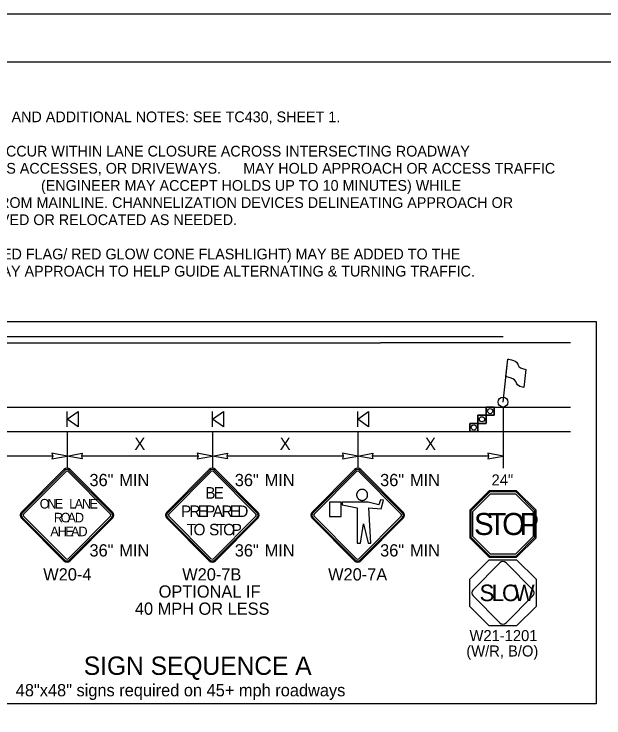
# Model space of a CAD drawing. Extents: x 99999.1 to 100095.7, y 99995 to 100010.7.
# Drawn here: x 100021.344 to 100025.2, y 100006.089 to 100010.687 of the extents above; entities that cross this region are included whole.
import ezdxf

# ---------------------------------------------------------------- set-up
doc = ezdxf.new("R2010")
doc.units = 0
for name, color, linetype in [('RD_ED_ShoulderPavedEdge', 7, 'Continuous'), ('RD_MK_LineDblYellowCenter', 7, 'Continuous'), ('RD_MK_LineEdgeWhite', 7, 'Continuous'), ('RD_MK_LineNoPass', 7, 'Continuous'), ('RD_MK_LineSkipCenter', 7, 'Continuous'), ('SH_DE_DetailHeading2Text', 7, 'Continuous'), ('SH_GI_GeneralNotesBodyText', 7, 'Continuous'), ('SH_GI_PlotLimits', 7, 'Continuous'), ('SH_GI_SheetBorder', 7, 'Continuous'), ('TR_SN_ConstructionSigns', 7, 'Continuous'), ('TR_WZ_FlaggingStation', 7, 'Continuous'), ('TR_WZ_PortableSignMountBlk-Org', 7, 'Continuous'), ('TR_WZ_TrafficCone', 7, 'Continuous'), ('TR_WZ_WorkZoneDetails', 7, 'Continuous'), ('TR_WZ_WorkZoneTextCurrent', 7, 'Continuous')]:
    doc.layers.add(name, color=color, linetype=linetype)

msp = doc.modelspace()

# ---------------------------------------------------------------- linework, layer by layer
at = {"layer": 'RD_ED_ShoulderPavedEdge'}
msp.add_line((100020.3, 100007.9602), (100024.9804, 100007.9602), dxfattribs=at)
at = {"layer": 'RD_MK_LineDblYellowCenter'}
for p, q in [((100020.3, 100008.5802), (100023.7402, 100008.5802)), ((100020.3, 100008.5402), (100023.7402, 100008.5402))]:
    msp.add_line(p, q, dxfattribs=at)
at = {"layer": 'RD_MK_LineEdgeWhite'}
msp.add_line((100020.3, 100008.1202), (100024.9804, 100008.1202), dxfattribs=at)
at = {"layer": 'RD_MK_LineNoPass'}
msp.add_line((100023.7402, 100008.5802), (100024.5402, 100008.5802), dxfattribs=at)
at = {"layer": 'RD_MK_LineSkipCenter'}
msp.add_lwpolyline([(100024.9804, 100008.5402), (100023.7402, 100008.5402)], dxfattribs=at)
at = {"layer": 'SH_GI_PlotLimits'}
msp.add_lwpolyline([(100019.0625, 99999.6875), (100036.0625, 99999.6875), (100036.0625, 100010.6875), (100019.0625, 100010.6875)], close=True, dxfattribs=at)
at = {"layer": 'SH_GI_SheetBorder'}
msp.add_line((100020, 100010.375), (100035.75, 100010.375), dxfattribs=at)
at = {"layer": 'TR_SN_ConstructionSigns'}
for p, q in [((100021.6703, 100007.712), (100021.3919, 100007.4336)), ((100021.6758, 100007.7065), (100021.3974, 100007.428)), ((100021.4051, 100007.4203), (100021.6835, 100007.6987)), ((100021.6968, 100007.6987), (100021.9752, 100007.4203)), ((100021.9829, 100007.428), (100021.7045, 100007.7065)), ((100021.9885, 100007.4336), (100021.71, 100007.712)), ((100022.6203, 100007.712), (100022.3419, 100007.4336)), ((100022.6258, 100007.7065), (100022.3474, 100007.428)), ((100022.3551, 100007.4203), (100022.6335, 100007.6987)), ((100022.6468, 100007.6987), (100022.9252, 100007.4203)), ((100022.9329, 100007.428), (100022.6545, 100007.7065)), ((100022.9385, 100007.4336), (100022.66, 100007.712)), ((100023.5703, 100007.712), (100023.2919, 100007.4336)), ((100023.5758, 100007.7065), (100023.2974, 100007.428)), ((100023.3051, 100007.4203), (100023.5835, 100007.6987)), ((100023.5968, 100007.6987), (100023.8752, 100007.4203)), ((100023.8829, 100007.428), (100023.6045, 100007.7065)), ((100023.8885, 100007.4336), (100023.61, 100007.712)), ((100023.6071, 100007.5803), (100023.6053, 100007.5796)), ((100023.6089, 100007.5809), (100023.6071, 100007.5803)), ((100023.6108, 100007.5814), (100023.6089, 100007.5809)), ((100023.6127, 100007.5818), (100023.6108, 100007.5814)), ((100023.6146, 100007.5821), (100023.6127, 100007.5818)), ((100023.6164, 100007.5823), (100023.6146, 100007.5821)), ((100023.6184, 100007.5824), (100023.6164, 100007.5823)), ((100023.6203, 100007.5824), (100023.6184, 100007.5824)), ((100023.6222, 100007.5823), (100023.6203, 100007.5824)), ((100023.6241, 100007.5821), (100023.6222, 100007.5823)), ((100023.626, 100007.5818), (100023.6241, 100007.5821)), ((100023.6279, 100007.5814), (100023.626, 100007.5818)), ((100023.6297, 100007.5809), (100023.6279, 100007.5814)), ((100023.6316, 100007.5803), (100023.6297, 100007.5809)), ((100023.6333, 100007.5796), (100023.6316, 100007.5803)), ((100023.5835, 100007.5502), (100023.5833, 100007.5483)), ((100023.5833, 100007.5483), (100023.5833, 100007.5464)), ((100023.5833, 100007.5464), (100023.5833, 100007.5445)), ((100023.5833, 100007.5445), (100023.5835, 100007.5426)), ((100023.5838, 100007.5522), (100023.5835, 100007.5502)), ((100023.5835, 100007.5426), (100023.5838, 100007.5407)), ((100023.5842, 100007.554), (100023.5838, 100007.5522)), ((100023.5838, 100007.5407), (100023.5842, 100007.5388)), ((100023.5846, 100007.5559), (100023.5842, 100007.554)), ((100023.5842, 100007.5388), (100023.5846, 100007.5369)), ((100023.5852, 100007.5577), (100023.5846, 100007.5559)), ((100023.5846, 100007.5369), (100023.5852, 100007.5351)), ((100023.5858, 100007.5595), (100023.5852, 100007.5577)), ((100023.5852, 100007.5351), (100023.5858, 100007.5333)), ((100023.5865, 100007.5613), (100023.5858, 100007.5595)), ((100023.5873, 100007.563), (100023.5865, 100007.5613)), ((100023.5883, 100007.5647), (100023.5873, 100007.563)), ((100023.5894, 100007.5664), (100023.5883, 100007.5647)), ((100023.5904, 100007.5679), (100023.5894, 100007.5664)), ((100023.5916, 100007.5694), (100023.5904, 100007.5679)), ((100023.5929, 100007.5709), (100023.5916, 100007.5694)), ((100023.5942, 100007.5722), (100023.5929, 100007.5709)), ((100023.5956, 100007.5735), (100023.5942, 100007.5722)), ((100023.5971, 100007.5747), (100023.5956, 100007.5735)), ((100023.5986, 100007.5759), (100023.5971, 100007.5747)), ((100023.6002, 100007.5769), (100023.5986, 100007.5759)), ((100023.6019, 100007.5779), (100023.6002, 100007.5769)), ((100023.6036, 100007.5788), (100023.6019, 100007.5779)), ((100023.6053, 100007.5796), (100023.6036, 100007.5788)), ((100023.6351, 100007.5788), (100023.6333, 100007.5796)), ((100023.6368, 100007.5779), (100023.6351, 100007.5788)), ((100023.6385, 100007.5769), (100023.6368, 100007.5779)), ((100023.64, 100007.5759), (100023.6385, 100007.5769)), ((100023.6416, 100007.5747), (100023.64, 100007.5759)), ((100023.643, 100007.5735), (100023.6416, 100007.5747)), ((100023.6445, 100007.5722), (100023.643, 100007.5735)), ((100023.6458, 100007.5709), (100023.6445, 100007.5722)), ((100023.647, 100007.5694), (100023.6458, 100007.5709)), ((100023.6482, 100007.5679), (100023.647, 100007.5694)), ((100023.6494, 100007.5664), (100023.6482, 100007.5679)), ((100023.6504, 100007.5647), (100023.6494, 100007.5664)), ((100023.6513, 100007.563), (100023.6504, 100007.5647)), ((100023.6521, 100007.5613), (100023.6513, 100007.563)), ((100023.6529, 100007.5595), (100023.6521, 100007.5613)), ((100023.6535, 100007.5577), (100023.6529, 100007.5595)), ((100023.6529, 100007.5333), (100023.6535, 100007.5351)), ((100023.6541, 100007.5559), (100023.6535, 100007.5577)), ((100023.6535, 100007.5351), (100023.6541, 100007.5369)), ((100023.6545, 100007.554), (100023.6541, 100007.5559)), ((100023.6541, 100007.5369), (100023.6545, 100007.5388)), ((100023.6549, 100007.5522), (100023.6545, 100007.554)), ((100023.6545, 100007.5388), (100023.6549, 100007.5407)), ((100023.6552, 100007.5502), (100023.6549, 100007.5522)), ((100023.6549, 100007.5407), (100023.6552, 100007.5426)), ((100023.6553, 100007.5483), (100023.6552, 100007.5502)), ((100023.6552, 100007.5426), (100023.6553, 100007.5445)), ((100023.6554, 100007.5464), (100023.6553, 100007.5483)), ((100023.6553, 100007.5445), (100023.6554, 100007.5464)), ((100024.4506, 100007.5722), (100024.3241, 100007.4457)), ((100024.4534, 100007.5655), (100024.3308, 100007.4429)), ((100024.3421, 100007.4383), (100024.4581, 100007.5542)), ((100024.6295, 100007.5722), (100024.4506, 100007.5722)), ((100024.6267, 100007.5655), (100024.4534, 100007.5655)), ((100024.4581, 100007.5542), (100024.6221, 100007.5542)), ((100024.6221, 100007.5542), (100024.7381, 100007.4383)), ((100024.7493, 100007.4429), (100024.6267, 100007.5655)), ((100024.7561, 100007.4457), (100024.6295, 100007.5722)), ((100023.4059, 100007.4991), (100023.4059, 100007.4044)), ((100023.4812, 100007.4991), (100023.4059, 100007.4991)), ((100023.4812, 100007.4044), (100023.4812, 100007.4991)), ((100023.6596, 100007.4991), (100023.4882, 100007.4991)), ((100023.4882, 100007.4991), (100023.4882, 100007.481)), ((100023.5858, 100007.5333), (100023.5865, 100007.5315)), ((100023.5865, 100007.5315), (100023.5873, 100007.5298)), ((100023.5873, 100007.5298), (100023.5883, 100007.5281)), ((100023.5883, 100007.5281), (100023.5894, 100007.5265)), ((100023.5894, 100007.5265), (100023.5904, 100007.5249)), ((100023.5904, 100007.5249), (100023.5916, 100007.5234)), ((100023.5916, 100007.5234), (100023.5929, 100007.522)), ((100023.5929, 100007.522), (100023.5942, 100007.5206)), ((100023.5942, 100007.5206), (100023.5956, 100007.5193)), ((100023.5956, 100007.5193), (100023.5971, 100007.5181)), ((100023.5971, 100007.5181), (100023.5986, 100007.5169)), ((100023.5986, 100007.5169), (100023.6002, 100007.5159)), ((100023.6002, 100007.5159), (100023.6019, 100007.5149)), ((100023.6019, 100007.5149), (100023.6036, 100007.514)), ((100023.6036, 100007.514), (100023.6053, 100007.5132)), ((100023.6053, 100007.5132), (100023.6071, 100007.5125)), ((100023.6071, 100007.5125), (100023.6089, 100007.5119)), ((100023.6089, 100007.5119), (100023.6108, 100007.5114)), ((100023.6108, 100007.5114), (100023.6127, 100007.511)), ((100023.6127, 100007.511), (100023.6146, 100007.5107)), ((100023.6146, 100007.5107), (100023.6164, 100007.5105)), ((100023.6164, 100007.5105), (100023.6184, 100007.5104)), ((100023.6184, 100007.5104), (100023.6203, 100007.5104)), ((100023.6203, 100007.5104), (100023.6222, 100007.5105)), ((100023.6222, 100007.5105), (100023.6241, 100007.5107)), ((100023.6241, 100007.5107), (100023.626, 100007.511)), ((100023.626, 100007.511), (100023.6279, 100007.5114)), ((100023.6279, 100007.5114), (100023.6297, 100007.5119)), ((100023.6297, 100007.5119), (100023.6316, 100007.5125)), ((100023.6316, 100007.5125), (100023.6333, 100007.5132)), ((100023.6333, 100007.5132), (100023.6351, 100007.514)), ((100023.6351, 100007.514), (100023.6368, 100007.5149)), ((100023.6368, 100007.5149), (100023.6385, 100007.5159)), ((100023.6385, 100007.5159), (100023.64, 100007.5169)), ((100023.64, 100007.5169), (100023.6416, 100007.5181)), ((100023.6416, 100007.5181), (100023.643, 100007.5193)), ((100023.643, 100007.5193), (100023.6445, 100007.5206)), ((100023.6445, 100007.5206), (100023.6458, 100007.522)), ((100023.6458, 100007.522), (100023.647, 100007.5234)), ((100023.647, 100007.5234), (100023.6482, 100007.5249)), ((100023.6482, 100007.5249), (100023.6494, 100007.5265)), ((100023.6494, 100007.5265), (100023.6504, 100007.5281)), ((100023.6504, 100007.5281), (100023.6513, 100007.5298)), ((100023.6513, 100007.5298), (100023.6521, 100007.5315)), ((100023.6521, 100007.5315), (100023.6529, 100007.5333)), ((100023.7291, 100007.482), (100023.6596, 100007.4991)), ((100023.7388, 100007.5148), (100023.7291, 100007.482)), ((100023.7588, 100007.5112), (100023.7388, 100007.5148)), ((100023.7438, 100007.4544), (100023.7588, 100007.5112)), ((100023.4882, 100007.481), (100023.5877, 100007.4612)), ((100023.5877, 100007.4612), (100023.5877, 100007.2309)), ((100023.6759, 100007.2309), (100023.6628, 100007.4613)), ((100023.6628, 100007.4613), (100023.7438, 100007.4544)), ((100024.3241, 100007.4457), (100024.3241, 100007.2668)), ((100024.3308, 100007.4429), (100024.3308, 100007.2696)), ((100024.7493, 100007.2696), (100024.7493, 100007.4429)), ((100024.7561, 100007.2668), (100024.7561, 100007.4457)), ((100021.3974, 100007.3993), (100021.6758, 100007.1209)), ((100021.6835, 100007.1286), (100021.4051, 100007.4071)), ((100021.9752, 100007.4071), (100021.6968, 100007.1286)), ((100021.7045, 100007.1209), (100021.9829, 100007.3993)), ((100022.3474, 100007.3993), (100022.6258, 100007.1209)), ((100022.6335, 100007.1286), (100022.3551, 100007.4071)), ((100022.9252, 100007.4071), (100022.6468, 100007.1286)), ((100022.6545, 100007.1209), (100022.9329, 100007.3993)), ((100023.2974, 100007.3993), (100023.5758, 100007.1209)), ((100023.5835, 100007.1286), (100023.3051, 100007.4071)), ((100023.4059, 100007.4044), (100023.4812, 100007.4044)), ((100023.8752, 100007.4071), (100023.5968, 100007.1286)), ((100023.6045, 100007.1209), (100023.8829, 100007.3993)), ((100024.3421, 100007.2742), (100024.3421, 100007.4383)), ((100024.7381, 100007.4383), (100024.7381, 100007.2742)), ((100021.3919, 100007.3938), (100021.6703, 100007.1154)), ((100021.71, 100007.1154), (100021.9885, 100007.3938)), ((100022.3419, 100007.3938), (100022.6203, 100007.1154)), ((100022.66, 100007.1154), (100022.9385, 100007.3938)), ((100023.2919, 100007.3938), (100023.5703, 100007.1154)), ((100023.6079, 100007.2309), (100023.6276, 100007.3576)), ((100023.61, 100007.1154), (100023.8885, 100007.3938)), ((100023.6276, 100007.3576), (100023.6579, 100007.2309)), ((100024.3241, 100007.2668), (100024.4506, 100007.1402)), ((100024.3308, 100007.2696), (100024.4534, 100007.147)), ((100024.4581, 100007.1582), (100024.3421, 100007.2742)), ((100024.7381, 100007.2742), (100024.6221, 100007.1582)), ((100024.6267, 100007.147), (100024.7493, 100007.2696)), ((100024.6295, 100007.1402), (100024.7561, 100007.2668)), ((100023.5877, 100007.2309), (100023.6079, 100007.2309)), ((100023.6579, 100007.2309), (100023.6759, 100007.2309)), ((100024.4506, 100007.1402), (100024.6295, 100007.1402)), ((100024.4534, 100007.147), (100024.6267, 100007.147)), ((100024.6221, 100007.1582), (100024.4581, 100007.1582)), ((100024.5197, 100007.1019), (100024.3444, 100006.9266)), ((100024.7357, 100006.9266), (100024.5604, 100007.1019)), ((100024.3444, 100006.8859), (100024.5197, 100006.7106)), ((100024.5604, 100006.7106), (100024.7357, 100006.8859))]:
    msp.add_line(p, q, dxfattribs=at)
msp.add_lwpolyline([(100024.7561, 100006.9957), (100024.7561, 100006.8168), (100024.6295, 100006.6902), (100024.4506, 100006.6902), (100024.3241, 100006.8168), (100024.3241, 100006.9957), (100024.4506, 100007.1222), (100024.6295, 100007.1222)], close=True, dxfattribs=at)
for centre, radius, start, end in [((100021.6902, 100007.6921), 0.0281, 45, 135), ((100022.6402, 100007.6921), 0.0281, 45, 135), ((100023.5902, 100007.6921), 0.0281, 45, 135), ((100021.6902, 100007.6921), 0.0203, 45, 135), ((100021.6902, 100007.6921), 0.00937, 45, 135), ((100022.6402, 100007.6921), 0.0203, 45, 135), ((100022.6402, 100007.6921), 0.00937, 45, 135), ((100023.5902, 100007.6921), 0.0203, 45, 135), ((100023.5902, 100007.6921), 0.00937, 45, 135), ((100021.4117, 100007.4137), 0.0281, 135, 225), ((100021.4117, 100007.4137), 0.0203, 135, 225), ((100021.4117, 100007.4137), 0.00937, 135, 225), ((100021.9686, 100007.4137), 0.00937, 315, 45), ((100021.9686, 100007.4137), 0.0203, 315, 45), ((100021.9686, 100007.4137), 0.0281, 315, 45), ((100022.3617, 100007.4137), 0.0281, 135, 225), ((100022.3617, 100007.4137), 0.0203, 135, 225), ((100022.3617, 100007.4137), 0.00937, 135, 225), ((100022.9186, 100007.4137), 0.00937, 315, 45), ((100022.9186, 100007.4137), 0.0203, 315, 45), ((100022.9186, 100007.4137), 0.0281, 315, 45), ((100023.3117, 100007.4137), 0.0281, 135, 225), ((100023.3117, 100007.4137), 0.0203, 135, 225), ((100023.3117, 100007.4137), 0.00937, 135, 225), ((100023.8686, 100007.4137), 0.00937, 315, 45), ((100023.8686, 100007.4137), 0.0203, 315, 45), ((100023.8686, 100007.4137), 0.0281, 315, 45), ((100021.6902, 100007.1353), 0.0203, 225, 315), ((100021.6902, 100007.1353), 0.00937, 225, 315), ((100022.6402, 100007.1353), 0.0203, 225, 315), ((100022.6402, 100007.1353), 0.00937, 225, 315), ((100023.5902, 100007.1353), 0.0203, 225, 315), ((100023.5902, 100007.1353), 0.00937, 225, 315), ((100021.6902, 100007.1353), 0.0281, 225, 315), ((100022.6402, 100007.1353), 0.0281, 225, 315), ((100023.5902, 100007.1353), 0.0281, 225, 315), ((100024.5401, 100007.0815), 0.0288, 45, 135), ((100024.3648, 100006.9062), 0.0288, 135, 225), ((100024.7153, 100006.9062), 0.0288, 315, 45), ((100024.5401, 100006.731), 0.0288, 225, 315)]:
    msp.add_arc(centre, radius, start, end, dxfattribs=at)
at = {"layer": 'TR_WZ_FlaggingStation'}
for p, q in [((100024.5402, 100008.1527), (100024.5722, 100008.4337)), ((100024.5592, 100008.3196), (100024.5723, 100008.434)), ((100024.6902, 100008.3662), (100024.6769, 100008.249)), ((100024.5592, 100008.3196), (100024.5592, 100008.3196))]:
    msp.add_line(p, q, dxfattribs=at)
for points in [[(100024.5723, 100008.434), (100024.578, 100008.4327), (100024.5958, 100008.4293), (100024.6097, 100008.4251), (100024.6193, 100008.419), (100024.6279, 100008.4143), (100024.6335, 100008.4075), (100024.6378, 100008.3996), (100024.6383, 100008.3934), (100024.6437, 100008.3842), (100024.6545, 100008.3768), (100024.6669, 100008.3716), (100024.6902, 100008.3662)], [(100024.6769, 100008.249), (100024.6687, 100008.2504), (100024.6511, 100008.255), (100024.6354, 100008.2655), (100024.6289, 100008.2761), (100024.625, 100008.2864), (100024.6159, 100008.2973), (100024.6049, 100008.3035), (100024.5876, 100008.3106), (100024.5592, 100008.3196)]]:
    msp.add_lwpolyline(points, dxfattribs=at)
msp.add_circle((100024.5402, 100008.1527), 0.0325, dxfattribs=at)
at = {"layer": 'TR_WZ_PortableSignMountBlk-Org'}
for p, q in [((100021.6902, 100007.9902), (100021.6902, 100008.0902)), ((100022.6402, 100007.9902), (100022.6402, 100008.0902)), ((100023.5902, 100007.9902), (100023.5902, 100008.0902))]:
    msp.add_line(p, q, dxfattribs=at)
for points in [[(100021.6902, 100008.0401), (100021.762, 100008.0902), (100021.762, 100007.9902)], [(100022.6402, 100008.0401), (100022.712, 100008.0902), (100022.712, 100007.9902)], [(100023.5902, 100008.0401), (100023.662, 100008.0902), (100023.662, 100007.9902)]]:
    msp.add_lwpolyline(points, close=True, dxfattribs=at)
at = {"layer": 'TR_WZ_TrafficCone'}
for points in [[(100024.4295, 100008.1202), (100024.4828, 100008.1202), (100024.4828, 100008.0669), (100024.4295, 100008.0669), (100024.4295, 100008.1202)], [(100024.4295, 100008.0669), (100024.4828, 100008.0669), (100024.4828, 100008.1202), (100024.4295, 100008.1202), (100024.4295, 100008.0669)], [(100024.3762, 100008.0669), (100024.4295, 100008.0669), (100024.4295, 100008.0136), (100024.3762, 100008.0136), (100024.3762, 100008.0669)], [(100024.3762, 100008.0136), (100024.4295, 100008.0136), (100024.4295, 100008.0669), (100024.3762, 100008.0669), (100024.3762, 100008.0136)], [(100024.3228, 100008.0136), (100024.3762, 100008.0136), (100024.3762, 100007.9602), (100024.3228, 100007.9602), (100024.3228, 100008.0136)], [(100024.3228, 100007.9602), (100024.3762, 100007.9602), (100024.3762, 100008.0136), (100024.3228, 100008.0136), (100024.3228, 100007.9602)]]:
    msp.add_lwpolyline(points, dxfattribs=at)
for centre in [(100024.4562, 100008.0936), (100024.4028, 100008.0402), (100024.3495, 100007.9869)]:
    msp.add_circle(centre, 0.0167, dxfattribs=at)
at = {"layer": 'TR_WZ_WorkZoneDetails'}
for p, q in [((100024.5402, 100008.1202), (100024.5402, 100007.7202)), ((100021.6902, 100007.9602), (100021.6902, 100007.7202)), ((100022.6402, 100007.9602), (100022.6402, 100007.7202)), ((100023.5902, 100007.9602), (100023.5902, 100007.7202)), ((100021.5964, 100007.8002), (100020.8339, 100007.8002)), ((100022.5464, 100007.8002), (100021.7839, 100007.8002)), ((100023.4964, 100007.8002), (100022.7339, 100007.8002)), ((100024.4464, 100007.8002), (100023.6839, 100007.8002))]:
    msp.add_line(p, q, dxfattribs=at)
for points in [[(100021.6902, 100007.8002), (100021.5919, 100007.8195), (100021.5964, 100007.8002), (100021.5919, 100007.781)], [(100021.6902, 100007.8002), (100021.7884, 100007.8195), (100021.7839, 100007.8002), (100021.7884, 100007.781)], [(100022.6402, 100007.8002), (100022.5419, 100007.8195), (100022.5464, 100007.8002), (100022.5419, 100007.781)], [(100022.6402, 100007.8002), (100022.7384, 100007.8195), (100022.7339, 100007.8002), (100022.7384, 100007.781)], [(100023.5902, 100007.8002), (100023.4919, 100007.8195), (100023.4964, 100007.8002), (100023.4919, 100007.781)], [(100023.5902, 100007.8002), (100023.6884, 100007.8195), (100023.6839, 100007.8002), (100023.6884, 100007.781)], [(100024.5402, 100007.8002), (100024.4419, 100007.8195), (100024.4464, 100007.8002), (100024.4419, 100007.781)]]:
    msp.add_lwpolyline(points, close=True, dxfattribs=at)
at = {"layer": 'TR_WZ_WorkZoneTextCurrent'}
msp.add_lwpolyline([(100020.1, 100008.6802), (100025.15, 100008.6802), (100025.15, 100006.1804), (100020.1, 100006.1804)], close=True, dxfattribs=at)

# ---------------------------------------------------------------- texts
at = {"layer": 'SH_DE_DetailHeading2Text'}
msp.add_text('SIGN SEQUENCE A', height=0.12, rotation=360, dxfattribs=at).set_placement((100021.7998, 100006.3705))
at = {"layer": 'SH_GI_GeneralNotesBodyText'}
for s, p in [('11. FOR LEGEND, TABLES, AND ADDITIONAL NOTES: SEE TC430, SHEET 1.', (100020.1, 100009.981)), ('12. WORK MAY BRIEFLY OCCUR WITHIN LANE CLOSURE ACROSS INTERSECTING ROADWAY ', (100020.1, 100009.757)), ('APPROACHES, BUSINESS ACCESSES, OR DRIVEWAYS. ', (100020.18, 100009.645)), ('MAY HOLD APPROACH OR ACCESS TRAFFIC ', (100022.8426, 100009.645)), (' (ENGINEER MAY ACCEPT HOLDS UP TO 10 MINUTES) WHILE ', (100021.494, 100009.533)), ('RESTRICTING TURNS FROM MAINLINE. CHANNELIZATION DEVICES DELINEATING APPROACH OR ', (100020.18, 100009.421)), ('ACCESS MAY BE REMOVED OR RELOCATED AS NEEDED.', (100020.18, 100009.309)), ('13. SINGLE AFAD (WITH RED FLAG/ RED GLOW CONE FLASHLIGHT) MAY BE ADDED TO THE ', (100020.1, 100009.085)), ('INTERSECTING ROADWAY APPROACH TO HELP GUIDE ALTERNATING & TURNING TRAFFIC.', (100020.18, 100008.973))]:
    msp.add_text(s, height=0.07, rotation=360, dxfattribs=at).set_placement(p)
at = {"layer": 'TR_SN_ConstructionSigns'}
for s, height, p in [('36"', 0.08, (100021.8369, 100007.6035)), ('MIN', 0.08, (100022.0319, 100007.6035)), ('36"', 0.08, (100022.7869, 100007.6035)), ('MIN', 0.08, (100022.9819, 100007.6035)), ('36"', 0.08, (100023.7369, 100007.6035)), ('MIN', 0.08, (100023.9319, 100007.6035)), ('36"', 0.08, (100021.8369, 100007.1439)), ('MIN', 0.08, (100022.0319, 100007.1439)), ('36"', 0.08, (100022.7869, 100007.1439)), ('MIN', 0.08, (100022.9819, 100007.1439)), ('36"', 0.08, (100023.7369, 100007.1439)), ('MIN', 0.08, (100023.9319, 100007.1439)), ('W20-4', 0.08, (100021.5347, 100006.9871)), ('W20-7B', 0.08, (100022.4432, 100006.9871)), ('W20-7A', 0.08, (100023.3969, 100006.9871)), ('OPTIONAL IF', 0.08, (100022.2892, 100006.8751)), ('40 MPH OR LESS', 0.08, (100022.1337, 100006.7631)), ('W21-1201', 0.072, (100024.3213, 100006.5913)), ('(W/R, B/O)', 0.072, (100024.3004, 100006.4905))]:
    msp.add_text(s, height=height, rotation=360, dxfattribs=at).set_placement(p)
for s, height, p in [('24"', 0.072, (100024.4654, 100007.6082)), ('B', 0.075, (100022.5939, 100007.5222)), ('E', 0.075, (100022.6482, 100007.5222)), ('O', 0.0625, (100021.5114, 100007.4574)), ('N', 0.0625, (100021.5608, 100007.4574)), ('E', 0.0625, (100021.6095, 100007.4574)), ('L', 0.0625, (100021.7039, 100007.4574)), ('A', 0.0625, (100021.7395, 100007.4574)), ('N', 0.0625, (100021.7883, 100007.4574)), ('E', 0.0625, (100021.837, 100007.4574)), ('P', 0.075, (100022.4353, 100007.4022)), ('R', 0.075, (100022.4905, 100007.4022)), ('E', 0.075, (100022.5437, 100007.4022)), ('P', 0.075, (100022.5932, 100007.4022)), ('A', 0.075, (100022.6431, 100007.4022)), ('R', 0.075, (100022.7004, 100007.4022)), ('E', 0.075, (100022.7536, 100007.4022)), ('D', 0.075, (100022.8031, 100007.4022)), ('R', 0.0625, (100021.6039, 100007.3668)), ('O', 0.0625, (100021.6483, 100007.3668)), ('A', 0.0625, (100021.6927, 100007.3668)), ('D', 0.0625, (100021.7414, 100007.3668)), ('S', 0.144, (100024.3507, 100007.2842)), ('T', 0.144, (100024.4443, 100007.2842)), ('O', 0.144, (100024.535, 100007.2842)), ('P', 0.144, (100024.6488, 100007.2842)), ('T', 0.075, (100022.4719, 100007.2822)), ('O', 0.075, (100022.517, 100007.2822)), ('S', 0.075, (100022.6185, 100007.2822)), ('T', 0.075, (100022.6656, 100007.2822)), ('O', 0.075, (100022.7107, 100007.2822)), ('P', 0.075, (100022.7664, 100007.2822)), ('A', 0.0625, (100021.5808, 100007.2762)), ('H', 0.0625, (100021.6295, 100007.2762)), ('E', 0.0625, (100021.6783, 100007.2762)), ('A', 0.0625, (100021.7158, 100007.2762)), ('D', 0.0625, (100021.7645, 100007.2762)), ('S', 0.108, (100024.3873, 100006.8522)), ('L', 0.108, (100024.4661, 100006.8522)), ('O', 0.108, (100024.5341, 100006.8522)), ('W', 0.108, (100024.6108, 100006.8522))]:
    msp.add_text(s, height=height, dxfattribs=at).set_placement(p)
at = {"layer": 'TR_WZ_WorkZoneTextCurrent'}
for p in [(100022.1304, 100007.8402), (100023.0804, 100007.8402), (100024.0304, 100007.8402)]:
    msp.add_text('X', height=0.08, rotation=360, dxfattribs=at).set_placement(p)
msp.add_text('48"x48" signs required on 45+ mph roadways', height=0.08, dxfattribs=at).set_placement((100021.3551, 100006.2305))

doc.saveas('drawing.dxf')
